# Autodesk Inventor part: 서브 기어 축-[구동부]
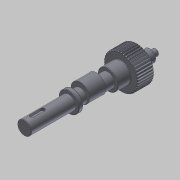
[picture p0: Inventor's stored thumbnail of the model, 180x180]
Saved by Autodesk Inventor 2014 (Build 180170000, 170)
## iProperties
Created: 2018-12
Part Number: 서브 기어 축-[구동부]
Material: 강철, 연강
Document SubType Name: Modeling
Designer: mduedu
Categories: <?xml version="1.0" encoding="UTF-16"?> <MemberInstance><Categories><FamilyTemplate><FamilyTemplateParameter ValueType="xs:double" Id="1" ObjectReferenceKey="da
Density: 7.86 g/cm^3
Appearance: Steel
Mass: 514.759 g
Surface Area: 160.366 cm^2
Volume: 65.491 cm^3
Author: mduedu
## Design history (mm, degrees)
sketch "Sketch1"
  geometry: C1 r 21.3 at (0, 0)
  constraints: 1 centre point
  dimensions: "d0" = 42.6 diameter of C1 (= da_da)
extrude "Extrusion1" new body sketch "Sketch1" distance "d1" = 20 (= da_b); taper "d2" = 0 deg
workplane "Work Plane2"
sketch "Sketch2"
  geometry: C1 r 21.3 at (0, 0) reference; C2 r 20.5 at (0, 0)
  constraints: 1 centre point, 1 coincident
  dimensions: "d3" = 41 diameter of C2 (= da_dw)
feature "피치 지름" sketch "Sketch2" dims "d4" = 10, "d5" = 0
workplane "Work Plane8"
workplane "Work Plane9"
chamfer "모따기1" distance "d49" = 1; stored, may be unused: second distance "d50" = 2, angle "d51" = 45 deg
sketch "스케치3"
  geometry: C1 r 12.5 at (0, 0); 1 further point
  constraints: 1 centre point, 1 coincident
  dimensions: "d52" = 25 diameter of C1
extrude "돌출2" join sketch "스케치3" distance "d53" = 16; taper "d54" = 0 deg
sketch "스케치4"
  geometry: C1 r 8.5 at (0, 0); 1 further point
  constraints: 1 centre point, 1 coincident
  dimensions: "d55" = 17 diameter of C1
extrude "돌출3" join sketch "스케치4" distance "d56" = 103; taper "d57" = 0 deg
sketch "스케치5"
  geometry: C1 r 7.5 at (0, 0); 1 further point
  constraints: 1 centre point, 1 coincident
  dimensions: "d58" = 15 diameter of C1
extrude "돌출4" join sketch "스케치5" distance "d59" = 16; taper "d60" = 0 deg
sketch "스케치6"
  geometry: C1 r 4 at (0, 0); 1 further point
  constraints: 1 centre point, 1 coincident
  dimensions: "d61" = 8 diameter of C1
extrude "돌출5" join sketch "스케치6" distance "d62" = 7; taper "d63" = 0 deg
chamfer "모따기2" distance "d64" = 0.5; stored, may be unused: second distance "d65" = 2, angle "d66" = 45 deg
fillet "모깎기1" dims "d67" = 0.5
feature "스퍼 기어" dims "da_b" = 20, "da_d" = 41, "da_aw" = 31, "da_da" = 42.6, "da_df" = 39.086, "da_dw" = 41, angle "da_beta" = 0 deg, "da_lefttooth" = 0, "da_righttooth" = 0
node "작업 평면11"
sketch "스케치7"
  geometry: C1 r 11.5 at (0, 3); C2 r 8.5 at (0, 0) reference; 1 further point
  constraints: 1 centre point, 1 tangent, 1 vertical alignment
  dimensions: "d69" = 3 distance of point (0, 0) C1.centre; "d70" = 23 diameter of C1 (derived)
extrude "돌출6" join sketch "스케치7" stored distance "d71" = 20; taper "d72" = 0 deg
node "작업 평면12"
sketch "스케치8"
  geometry: C1 r 12.5 at (0, 0) reference; C2 r 12.5 at (0, 0) reference; 1 further point
extrude "돌출7" join sketch "스케치8" distance "d74" = 5; taper "d75" = 0 deg
chamfer "모따기3" distance "d76" = 0.5; stored, may be unused: second distance "d77" = 2, angle "d78" = 45 deg
sketch "스케치9"
  geometry: L1 (-8, 139)-(8, 139) reference; L2 (0, 139)-(0, 0); L3 (-8.5, 84)-(-8.5, 138.5) reference; L4 (-8.5, 115)-(0, 115); L5 (-8.5, 115)-(-8.5, 113.5); L6 (-8.5, 113.5)-(-7, 115); L7 (-7, 115)-(-8.5, 115)
  constraints: 10 end point, 4 point on line, 2 perpendicular, 1 collinear, 1 midpoint
  dimensions: "d79" = 24 distance between parallel lines of L4 L1; "d80" = 3 diameter of L5.end L4; "d81" = 45 deg angle of L6 L3
revolve "회전1" sketch "스케치9" stored, may be unused: angle "d82" = 90 deg
sketch "스케치10"
  geometry: L1 (-8.5, 116.5)-(-7, 115) reference; L2 (-8.5, 113.5)-(-7, 115) reference; 2 further points
  constraints: 1 coincident
node "작업점1"
node "작업 평면13"
sketch "스케치11"
  geometry: L1 (-2.5, 93.5)-(-2.5, 80.5); L2 (2.5, 80.5)-(2.5, 93.5); L3 (-8, 103)-(8, 103) reference; A1 r 2.5 centre (0, 93.5) between (2.5, 93.5) and (-2.5, 93.5); A2 r 2.5 centre (0, 80.5) between (-2.5, 80.5) and (2.5, 80.5); 1 further point
  constraints: 4 end point, 4 point on circle, 4 tangent, 2 centre point, 2 vertical alignment, 1 parallel
  dimensions: "d83" = 7 distance edge to line of A1 L3; "d84" = 18 dimension on A2 A1; "d85" = 5 distance between parallel lines of L1 L2
extrude "돌출8" cut sketch "스케치11" distance "d86" = 3; taper "d87" = 0 deg
sketch "스케치12" dims "d88" = 32
  geometry: C1 r 0.5 at (0, -16); 2 further points
  constraints: 2 vertical alignment, 1 centre point, 1 coincident, 2 other
  dimensions: "d89" = 1 diameter of C1
extrude "돌출9" join sketch "스케치12" distance "d90" = 0.3; taper "d91" = 0 deg
sketch "스케치13"
  geometry: C1 r 11.5 at (0, 3) reference; 1 further point
  node "절단 모서리 투영1"
body "Solid1"
body "Srf1"
node "투영된 루프1"
other parameters: "d16" = 31 (= da_aw), "d17" = 0, "d34" = 0.76624 (computed from da_z), "d39" = 0, "d41" = 0, "d43" = 31 (= da_aw), "d46" = 31 (= da_aw), "d47" = 0, "d48" = 0, "d68" = 24, "d73" = 48
